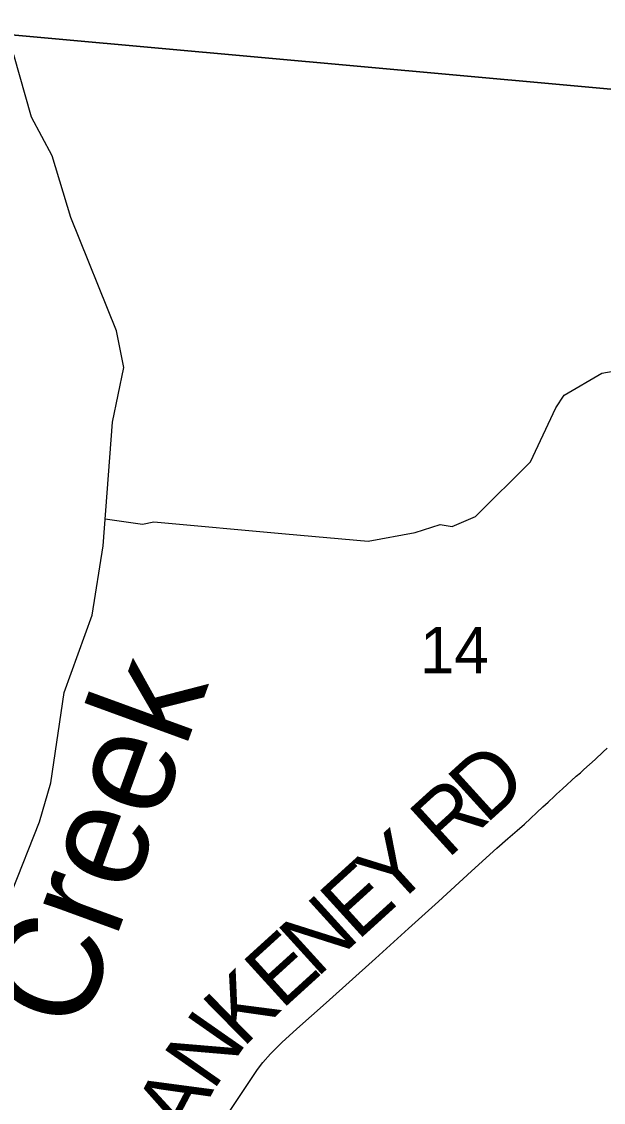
# Model space of a CAD drawing. Extents: x 1410790 to 1770854, y 448063 to 770588.
# Drawn here: x 1544730 to 1547506, y 628670 to 633827 of the extents above; entities that cross this region are included whole.
import ezdxf

# ---------------------------------------------------------------- set-up
doc = ezdxf.new("R2010")
doc.units = 0
for name, color, linetype in [('GM_X_Minor_River', 7, 'Continuous'), ('GM_X_Minor_River_Text', 7, 'Continuous'), ('GM_X_Section', 7, 'Continuous'), ('GM_X_Section_Text', 7, 'Continuous'), ('GM_X_Township_Road', 7, 'Continuous'), ('GM_X_Township_Road_Text', 7, 'Continuous')]:
    doc.layers.add(name, color=color, linetype=linetype)

msp = doc.modelspace()

# ---------------------------------------------------------------- linework, layer by layer
at = {"layer": 'GM_X_Minor_River'}
for points in [[(1544550.7, 629340), (1544815.8, 630008), (1544869.4, 630195.3), (1544933.7, 630625.1), (1545066.9, 630995.2), (1545119.3, 631324.9), (1545164.6, 631915.5), (1545217.6, 632177), (1545182.9, 632352.2), (1544964.9, 632892.4), (1544876.4, 633187.1), (1544777.7, 633371.7), (1544693.3, 633668.3)], [(1546608.2, 631388.7), (1546727.1, 631426.8), (1546785.1, 631417.8), (1546896.2, 631466), (1547159.2, 631726.2), (1547279.9, 631984.7), (1547319, 632044.2), (1547499.2, 632149.4), (1547553.5, 632158.5), (1547839.2, 632097.4), (1547959.1, 632197.7), (1548155.4, 632186.3), (1548257.4, 632172.5), (1548383, 632130.2), (1548457.2, 632131), (1548564.7, 632203.3), (1548821.3, 632321.2)], [(1545129.3, 631454.9), (1545307.5, 631429.1), (1545361.8, 631439.9), (1545989.6, 631382.2), (1546383.5, 631347.5), (1546608.2, 631388.7)]]:
    msp.add_lwpolyline(points, dxfattribs=at)
at = {"layer": 'GM_X_Section'}
for points in [[(1550230.3, 638666.5), (1549719.6, 633308.3), (1544399.7, 633789.9), (1544904.4, 639125.6)], [(1544399.7, 633789.9), (1549719.6, 633308.3), (1549189.3, 627980.4), (1543911.7, 628488)]]:
    msp.add_lwpolyline(points, close=True, dxfattribs=at)
at = {"layer": 'GM_X_Township_Road'}
msp.add_lwpolyline([(1545703.8, 628597.1), (1545778.9, 628712.6), (1545856, 628826.6), (1545881.6, 628860.4), (1545917.9, 628902.2), (1545971.3, 628955), (1546044, 629021.2), (1546184.1, 629145.1), (1546418.4, 629355.7), (1546576.4, 629499), (1546720, 629628.7), (1546876.9, 629773.2), (1546998.3, 629883.5), (1547049.7, 629929.3), (1547094.8, 629967), (1547129.5, 629997.2), (1547218.1, 630080.2), (1547242.2, 630102.4), (1547273, 630131.4), (1547282.2, 630140.5), (1547310.8, 630166.8), (1547376.5, 630225.8), (1547396.4, 630242.7), (1547413.6, 630258), (1547467, 630306.6), (1547505.6, 630342.1), (1547524.9, 630360)], dxfattribs=at)

# ---------------------------------------------------------------- texts
at = {"layer": 'GM_X_Minor_River_Text'}
msp.add_text('Creek', height=499.9, rotation=69.9449, dxfattribs=at).set_placement((1545013.1, 628991.7))
at = {"layer": 'GM_X_Section_Text'}
msp.add_text('14', height=221, rotation=0, dxfattribs=at).set_placement((1546631, 630717.5))
at = {"layer": 'GM_X_Township_Road_Text'}
for s, rotation, p in [('D', 42.2776, (1546944.5, 629993.7)), ('R', 42.2792, (1546762.2, 629828)), ('Y', 42.2787, (1546498.5, 629588.2)), ('E', 42.2777, (1546332.5, 629437.2)), ('N', 42.2815, (1546137.1, 629259.6)), ('E', 42.308, (1545971.2, 629108.6)), ('K', 44.5093, (1545785.2, 628925.6)), ('N', 55.0626, (1545643.4, 628720.4)), ('A', 62.1462, (1545525.2, 628495.3))]:
    msp.add_text(s, height=300, rotation=rotation, dxfattribs=at).set_placement(p)

doc.saveas('drawing.dxf')
